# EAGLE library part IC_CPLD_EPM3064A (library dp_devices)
64 Macrocells 3.3V CPLD
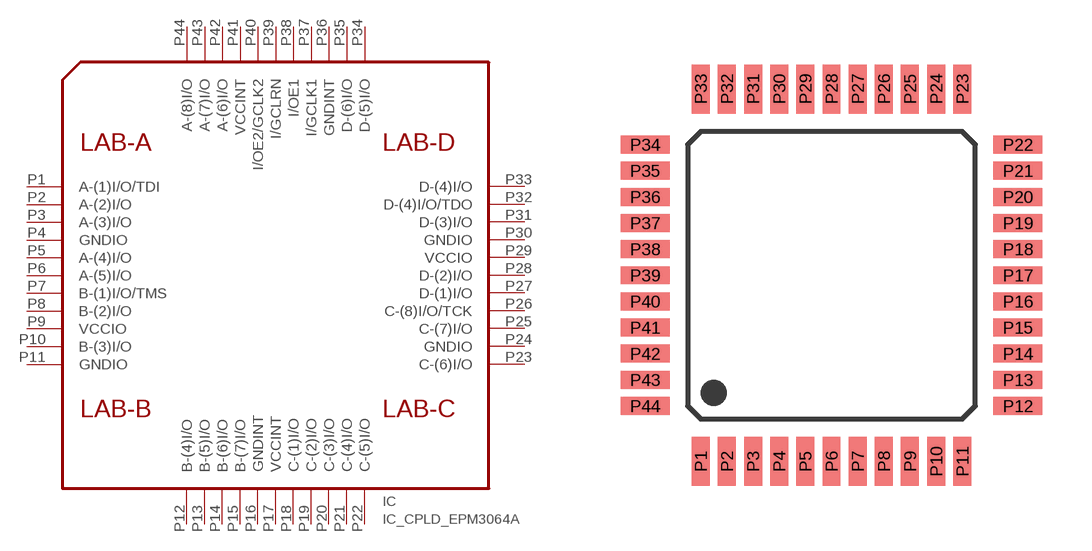
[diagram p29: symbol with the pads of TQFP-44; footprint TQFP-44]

Designator prefix IC

## IC_CPLD_EPM3064A-TQFP44  [TQFP-44]
P1  A-(1)I/O/TDI
P2  A-(2)I/O
P3  A-(3)I/O
P4  GNDIO  sup
P5  A-(4)I/O
P6  A-(5)I/O
P7  B-(1)I/O/TMS
P8  B-(2)I/O
P9  VCCIO  sup
P10  B-(3)I/O
P11  GNDIO  sup
P12  B-(4)I/O
P13  B-(5)I/O
P14  B-(6)I/O
P15  B-(7)I/O
P16  GNDINT  sup
P17  VCCINT  sup
P18  C-(1)I/O
P19  C-(2)I/O
P20  C-(3)I/O
P21  C-(4)I/O
P22  C-(5)I/O
P23  C-(6)I/O
P24  GNDIO  sup
P25  C-(7)I/O
P26  C-(8)I/O/TCK
P27  D-(1)I/O
P28  D-(2)I/O
P29  VCCIO  sup
P30  GNDIO  sup
P31  D-(3)I/O
P32  D-(4)I/O/TDO
P33  D-(4)I/O
P34  D-(5)I/O
P35  D-(6)I/O
P36  GNDINT  sup
P37  I/GCLK1
P38  I/OE1
P39  I/GCLRN
P40  I/OE2/GCLK2
P41  VCCINT  sup
P42  A-(6)I/O
P43  A-(7)I/O
P44  A-(8)I/O

## Footprint TQFP-44 (pad centres in mm)
smd 0.55 x 1.5: P1 -4,-5.7; P2 -3.2,-5.7; P3 -2.4,-5.7; P4 -1.6,-5.7; P5 -0.8,-5.7; P6 0,-5.7; P7 0.8,-5.7; P8 1.6,-5.7; P9 2.4,-5.7; P10 3.2,-5.7; P11 4,-5.7; P23 4,5.7; P24 3.2,5.7; P25 2.4,5.7; P26 1.6,5.7; P27 0.8,5.7; P28 0,5.7; P29 -0.8,5.7; P30 -1.6,5.7; P31 -2.4,5.7; P32 -3.2,5.7; P33 -4,5.7
smd 1.5 x 0.55: P12 5.7,-4; P13 5.7,-3.2; P14 5.7,-2.4; P15 5.7,-1.6; P16 5.7,-0.8; P17 5.7,0; P18 5.7,0.8; P19 5.7,1.6; P20 5.7,2.4; P21 5.7,3.2; P22 5.7,4; P34 -5.7,4; P35 -5.7,3.2; P36 -5.7,2.4; P37 -5.7,1.6; P38 -5.7,0.8; P39 -5.7,0; P40 -5.7,-0.8; P41 -5.7,-1.6; P42 -5.7,-2.4; P43 -5.7,-3.2; P44 -5.7,-4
